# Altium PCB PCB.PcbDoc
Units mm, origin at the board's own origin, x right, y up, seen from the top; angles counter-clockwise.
Board outline 49.15 x 32.89 mm, 2 copper layers (Top Layer, Bottom Layer); 7 components, 7 nets, 17 pads, 2 vias.
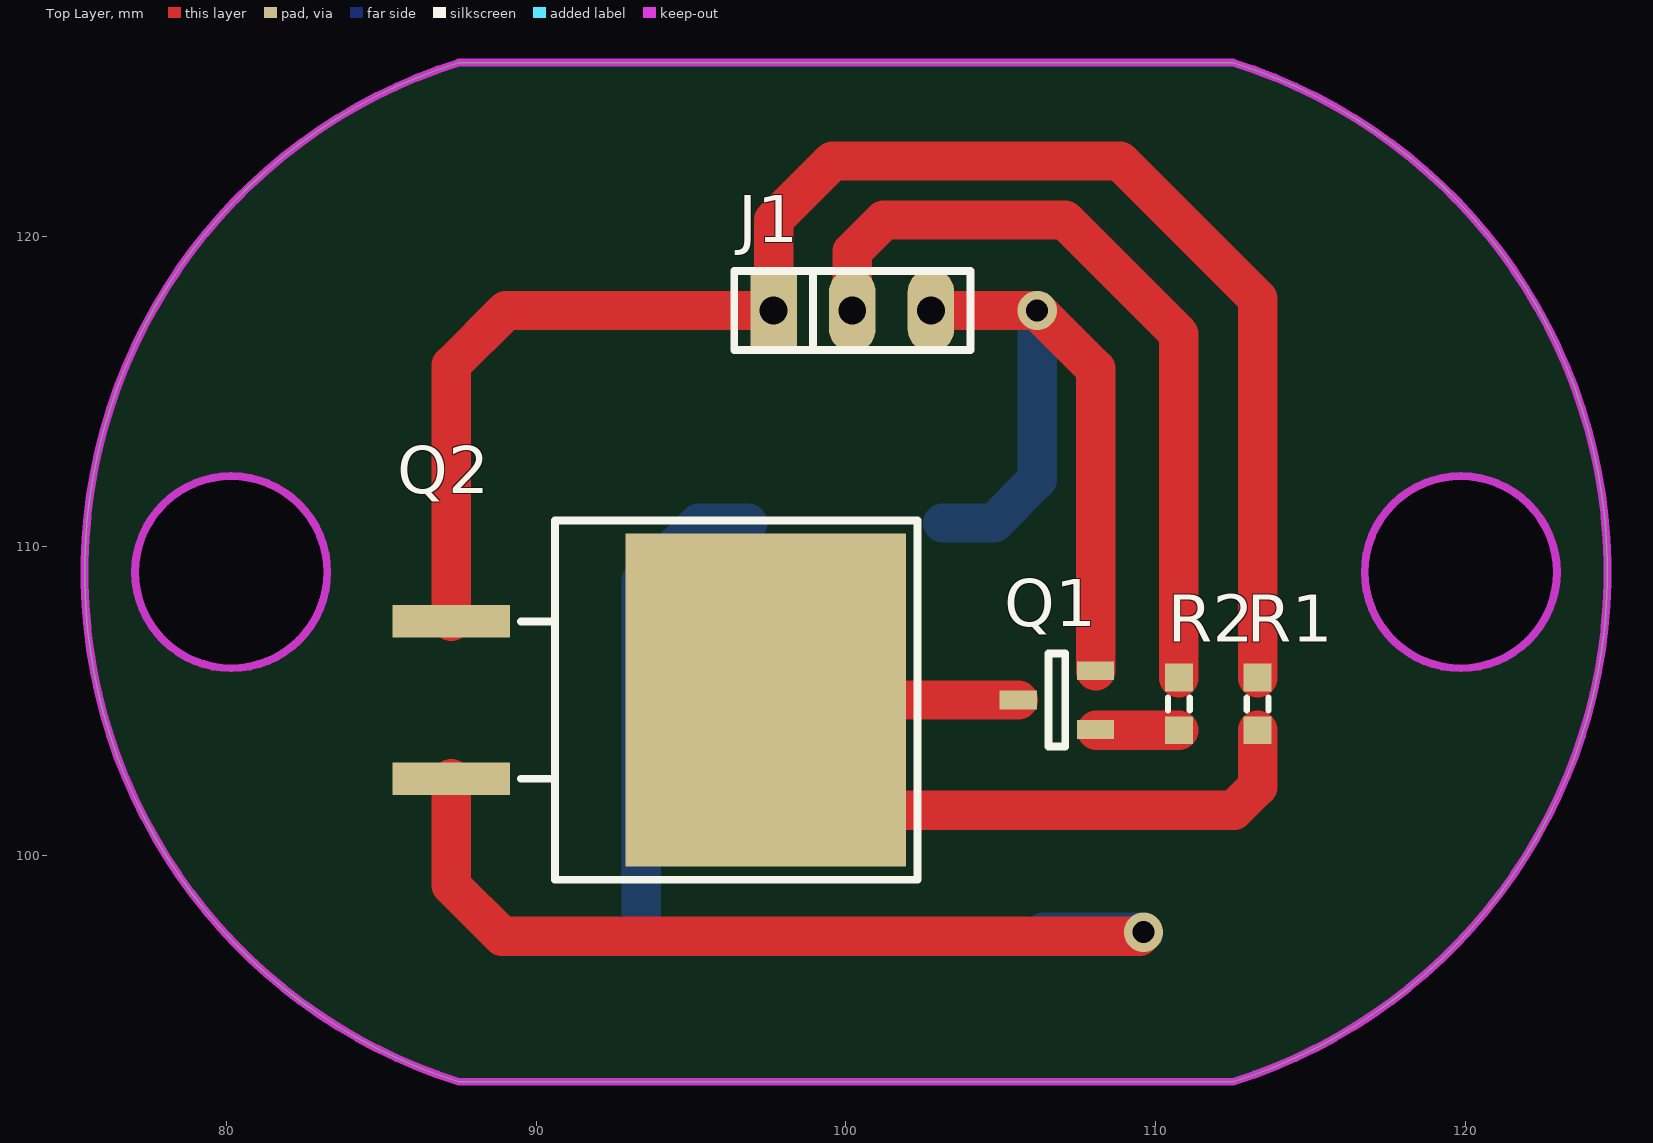
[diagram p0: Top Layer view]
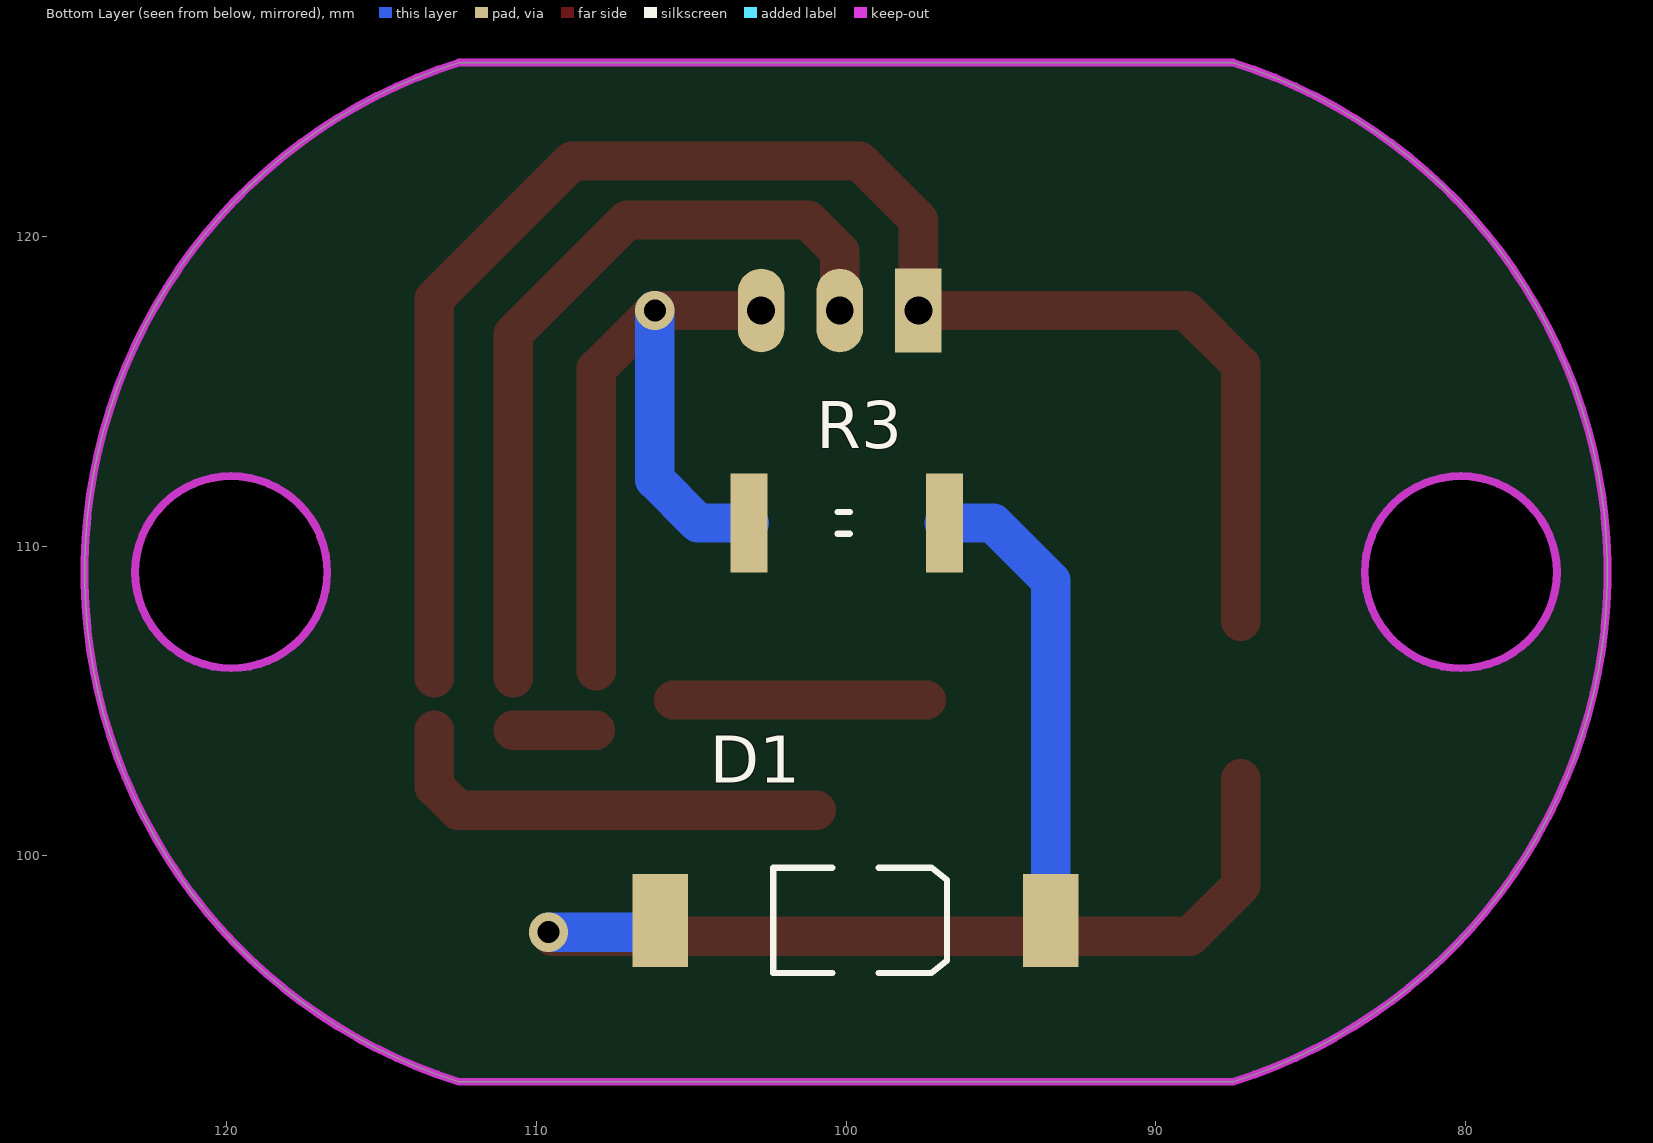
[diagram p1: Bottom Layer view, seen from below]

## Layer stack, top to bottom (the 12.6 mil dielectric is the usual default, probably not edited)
Top Layer: signal copper 0.0356
Dielectric: dielectric 0.32, FR-4, Dk 4.8
Bottom Layer: signal copper 0.0356

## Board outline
87.5,92.71 cw(c92.657,109.156) 87.5,125.603 112.5,125.603 cw(c107.343,109.156) 112.5,92.71
cut-out: 80.157,106.056 cw(c80.157,109.156) 77.057,109.156 cw(c80.157,109.156) 80.157,112.256 cw(c80.157,109.156) 83.257,109.156 cw(c80.157,109.156)
cut-out: 116.743,109.156 ccw(c119.843,109.156) 119.843,106.056 ccw(c119.843,109.156) 122.943,109.156 ccw(c119.843,109.156) 119.843,112.256 ccw(c119.843,109.156)

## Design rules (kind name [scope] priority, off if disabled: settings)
Clearance [All] p1: gap=0.254
PolygonConnect [All] p1: connectstyle=Relief reliefconductorwidth=0.254 reliefentries=4 polygonreliefangle="90 Angle" airgapwidth=0.254
RoutingVias [All] p1: holewidth=0.711 width=1.27 viastyle="Through Hole" minholewidth=0.711 minwidth=1.27 maxholewidth=0.711 maxwidth=1.27
SolderMaskExpansion [All] p1: expansion=0.102
Width [All] p1: maxlimit=2.032 minlimit=0.254 preferedwidth=0.254 minimp=50.000000 maximp=50.000000 favimp=50.000000
28 further rules are at their usual default settings.

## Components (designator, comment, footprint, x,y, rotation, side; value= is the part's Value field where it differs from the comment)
D1 "LED3" 3.5X2.8X1.9 99.695,97.917 r180 bottom
J1 "CON3" SIP-3 97.663,117.602 r0 top
Q1 "NPN" SOT-23 106.807,105.029 r90 top
Q2 "IRF540" TO-263-2 97.409,105.029 r270 top
R1 "10k" J1-0603#1 113.284,104.902 r90 top
R2 "10k" J1-0603#1 110.744,104.902 r270 top
R3 "12" J1-0603#2 100.076,110.744 r180 bottom

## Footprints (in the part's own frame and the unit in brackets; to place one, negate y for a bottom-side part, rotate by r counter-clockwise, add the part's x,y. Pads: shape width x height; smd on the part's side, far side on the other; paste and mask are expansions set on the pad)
3.5X2.8X1.9 [mm] "SM LED; 2 C-Bend Leads; Body 3.5 x 2.8 x 1.9 mm, inc leads (LxWxH typ)"
  rect 1.8x3 smd: 1(-6.3,0) 2(6.3,0)
  silkscreen extent -2.65,-1.7 2.95,1.7
J1-0603#1 [mm] "Chip Resistor, Body 1.6x0.8mm, IPC High Density"
  rect 0.9x0.9 smd: 1(-0.85,0) 2(0.85,0)
  silkscreen extent -0.2,-0.35 0.2,0.35, body extent -0.85,-0.48 0.85,0.48, height 0.9
J1-0603#2 [mm] "Chip Resistor, Body 1.6x0.8mm, IPC High Density"
  rect 1.2x3.2 smd: 1(-3.05,0) 2(3.25,0)
  silkscreen extent -0.2,-0.35 0.2,0.35, body extent -0.85,-0.48 0.85,0.48, height 0.9
SIP-3 [mm]
  rect 1.5x2.7 hole 0.9: 1(0,0)
  oval 1.5x2.7 hole 0.9: 2(2.54,0) 3(5.08,0)
  silkscreen extent -1.27,-1.27 6.35,1.27
SOT-23 [mm] "SOT-23-3"
  rect 0.6x1.2 smd: 1(-0.95,-1.25) 2(0.95,-1.25) 3(0,1.25)
  silkscreen extent -1.5,-0.27 1.5,0.27, body extent -1.46,-1.28 1.46,1.27, height 0.99
TO-263-2 [mm] "TO-263, D2PAK, 2PIN"
  rect 1.05x3.8 smd: 1(-2.54,-10.15) 3(2.54,-10.15)
  rect 10.75x9.05 smd: 4(0,0)
  silkscreen extent -5.8,-7.9 5.8,4.9, body extent -5.08,-11.39 5.08,3.87, height 5.01

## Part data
D1: "Typical BLUE SiC LED"
J1: "SOCKET"
Q1: library part BC847, "NPN Bipolar Transistor"
Q2: "N-Channel MOSFET"
R1 R2 R3: library part Res3, "Resistor"

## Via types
v1: diameter 1.27, hole 0.711, Top Layer to Bottom Layer, 2 vias

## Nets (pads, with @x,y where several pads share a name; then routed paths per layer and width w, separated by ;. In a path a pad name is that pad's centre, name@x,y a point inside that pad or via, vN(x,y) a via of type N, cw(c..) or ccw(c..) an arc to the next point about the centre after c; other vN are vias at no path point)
GND: J1.3 Q1.2 R3.1 | length 24.9
  Top Layer w1.27: J1.3 v1(106.172,117.602) 108.057,115.717 Q1.2
  Bottom Layer w1.27: R3.1 104.775,110.744 106.172,112.141 v1(106.172,117.602)
NetD1_1: D1.1 Q2.3 | length 29.6
  Top Layer w1.27: Q2.3 87.259,99.05 88.9,97.409 v1@109.474,97.409
  Bottom Layer w1.27: D1.1@106.376,97.536 v1(109.601,97.536)
NetD1_2: D1.2 R3.2 | length 15.2
  Bottom Layer w1.27: D1.2 93.395,108.889 95.25,110.744 R3.2
NetJ1_2: J1.2 R2.1 | length 25.5
  Top Layer w1.27: J1.2 100.203,119.507 101.219,120.523 107.061,120.523 110.744,116.84 R2.1
NetQ1_1: Q1.1 R2.2 | length 2.7
  Top Layer w1.27: Q1.1@108.084,104.052 R2.2
NetQ1_3: Q1.3 Q2.4 R1.1 | length 22.6
  Top Layer w1.27: Q2.4 Q1.3 ; Q2.4@100.965,101.473 112.522,101.473 113.284,102.235 R1.1
VCC: J1.1 Q2.1 R1.2 | length 52.8
  Top Layer w1.27: Q2.1 87.259,115.834 89.027,117.602 J1.1 97.663,120.523 99.568,122.428 108.839,122.428 113.284,117.983 R1.2

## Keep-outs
Keep-Out Layer:
  circle w0.254: c119.843,109.156 r3.1
  circle w0.254: c80.157,109.156 r3.1
  lines w0.254: 87.5,92.71 cw(c92.657,109.156) 87.5,125.603 112.5,125.603 cw(c107.343,109.156) 112.5,92.71 87.5,92.71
